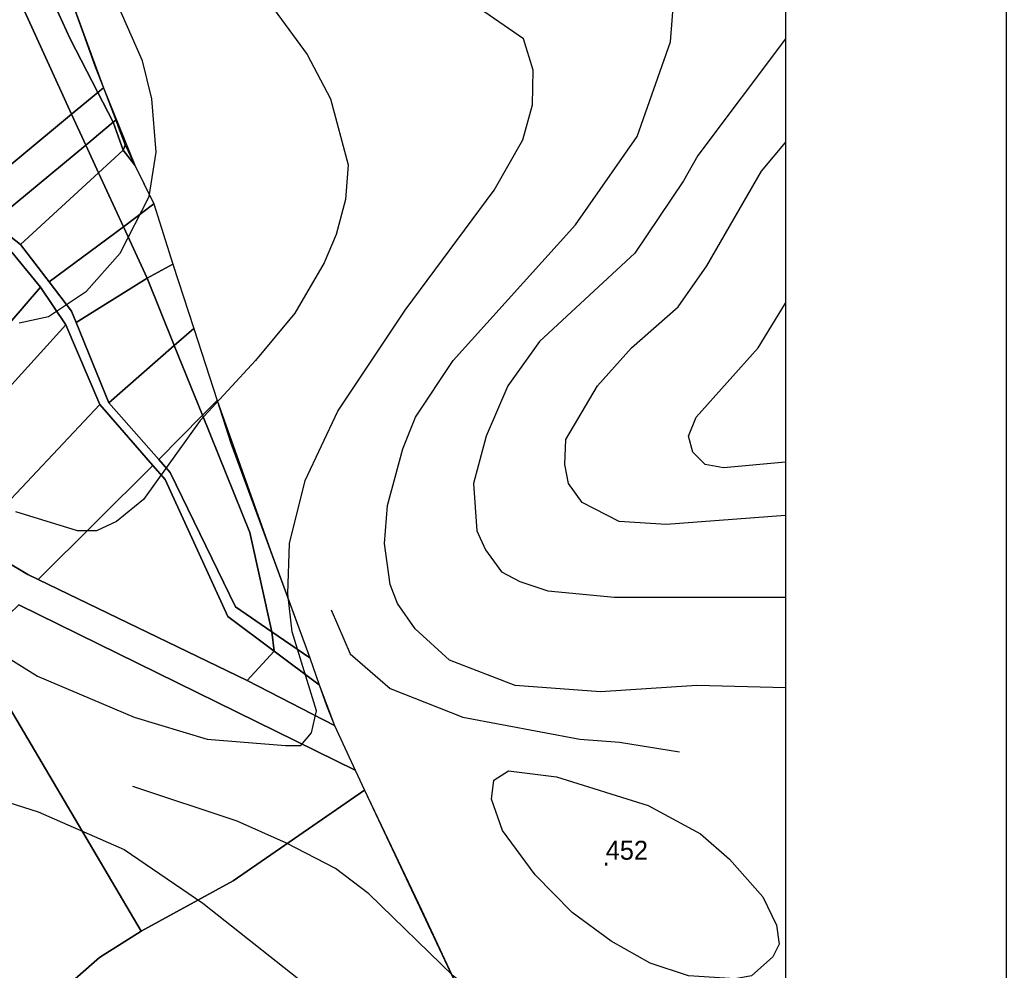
# Model space of a CAD drawing. Extents: x -510989 to -501240, y -1184665 to -1176098.
# Drawn here: x -508331.7 to -508019.1, y -1180014.3 to -1179713 of the extents above; entities that cross this region are included whole.
import ezdxf

# ---------------------------------------------------------------- set-up
doc = ezdxf.new("R2010")
doc.units = 0
for name, color, linetype in [('lesni_pozemek', 7, 'Continuous'), ('ostatni_plocha_x_ostatni_komunikace', 7, 'Continuous'), ('ostatni_plocha_x_silnice', 7, 'Continuous'), ('popis', 7, 'Continuous'), ('rozpiska', 7, 'Continuous'), ('vrstevnice_01', 7, 'Continuous'), ('vrstevnice_02', 7, 'Continuous'), ('vrstevnice_03', 7, 'Continuous'), ('vrstevnice_05', 7, 'Continuous')]:
    doc.layers.add(name, color=color, linetype=linetype)

msp = doc.modelspace()

# ---------------------------------------------------------------- linework, layer by layer
at = {"layer": 'lesni_pozemek'}
for points in [[(-508323.04, -1179685.4), (-508311.57, -1179717.24), (-508307.73, -1179727.9), (-508305.17, -1179734.59), (-508306.93, -1179736.06), (-508315.72, -1179719.07), (-508328.5, -1179691.06)], [(-508335.49, -1179698.31), (-508315.24, -1179742.94), (-508348.72, -1179770.69), (-508349.45, -1179770.12), (-508374.33, -1179736.49)], [(-508306.93, -1179736.06), (-508305.17, -1179734.59), (-508301.26, -1179744.83), (-508302.06, -1179745.49)], [(-508310.75, -1179752.69), (-508340.36, -1179777.21), (-508348.72, -1179770.69), (-508315.24, -1179742.94)], [(-508302.06, -1179745.49), (-508301.26, -1179744.83), (-508301.01, -1179745.49), (-508300.82, -1179745.98), (-508300.48, -1179746.87), (-508298.23, -1179752.78), (-508298.86, -1179754.33)], [(-508306.69, -1179761.51), (-508331.42, -1179784.18), (-508340.36, -1179777.21), (-508310.75, -1179752.69)], [(-508298.86, -1179754.33), (-508298.23, -1179752.78), (-508297.34, -1179754.61), (-508296.57, -1179756.18), (-508295.18, -1179759.04)], [(-508298.83, -1179778.58), (-508322.34, -1179796.08), (-508331.42, -1179784.18), (-508306.69, -1179761.51)], [(-508291.31, -1179794.91), (-508313.8, -1179808.92), (-508315.24, -1179805.39), (-508322.34, -1179796.08), (-508298.83, -1179778.58)], [(-508334.12, -1179786.6), (-508325.1, -1179797.79), (-508353.02, -1179830.13), (-508377.34, -1179854.07), (-508388.85, -1179845.53), (-508355.81, -1179815.14)], [(-508291.31, -1179794.91), (-508282.83, -1179815.88), (-508282.69, -1179816.22), (-508303.46, -1179834.36), (-508313.8, -1179808.92)], [(-508325.1, -1179797.79), (-508317.01, -1179809.73), (-508365.34, -1179862.96), (-508377.34, -1179854.07), (-508353.02, -1179830.13)], [(-508317.01, -1179809.73), (-508306.28, -1179834.94), (-508346.11, -1179877.21), (-508365.34, -1179862.96)], [(-508282.69, -1179816.22), (-508273.74, -1179838.34), (-508287.58, -1179852.38), (-508303.46, -1179834.36)], [(-508306.28, -1179834.94), (-508289.48, -1179854.27), (-508325.79, -1179890.38), (-508329.1, -1179888.78), (-508336.21, -1179884.55), (-508346.11, -1179877.21)], [(-508273.74, -1179838.34), (-508258.72, -1179875.46), (-508251.76, -1179906.97), (-508263.28, -1179899.04), (-508283.99, -1179856.46), (-508287.58, -1179852.38)], [(-508289.48, -1179854.27), (-508285.58, -1179858.75), (-508265.71, -1179902.1), (-508251.05, -1179913.07), (-508259.65, -1179922.4), (-508325.79, -1179890.38)], [(-508347.37, -1179913.24), (-508331.91, -1179898.4), (-508225.42, -1179950.88), (-508222.42, -1179957.19), (-508264.07, -1179985.88), (-508293.14, -1180001.85), (-508338.56, -1179924.99)], [(-508338.56, -1179924.99), (-508293.14, -1180001.85), (-508306.41, -1180010.22), (-508325.34, -1180026.8), (-508351.58, -1180000.65), (-508360.15, -1179982.23), (-508367.63, -1179961.39), (-508373.72, -1179938.52), (-508347.37, -1179913.24)], [(-508264.07, -1179985.88), (-508222.42, -1179957.19), (-508204.32, -1179995.16), (-508177.34, -1180053.09), (-508152.46, -1180106.83), (-508173.6, -1180123.17), (-508192.01, -1180134.69), (-508215.78, -1180151.38), (-508240.41, -1180170.53), (-508260.19, -1180138.45), (-508277.13, -1180118.72), (-508286.73, -1180111.41), (-508303.87, -1180065.86), (-508325.34, -1180026.8), (-508306.41, -1180010.22), (-508293.14, -1180001.85)]]:
    msp.add_lwpolyline(points, close=True, dxfattribs=at)
at = {"layer": 'ostatni_plocha_x_ostatni_komunikace'}
for points in [[(-508328.5, -1179691.06), (-508315.72, -1179719.07), (-508306.93, -1179736.06), (-508315.24, -1179742.94), (-508335.49, -1179698.31)], [(-508315.24, -1179742.94), (-508306.93, -1179736.06), (-508302.06, -1179745.49), (-508310.75, -1179752.69)], [(-508302.06, -1179745.49), (-508298.86, -1179754.33), (-508306.69, -1179761.51), (-508310.75, -1179752.69)], [(-508298.86, -1179754.33), (-508295.18, -1179759.04), (-508289.71, -1179770.24), (-508289.15, -1179771.38), (-508298.83, -1179778.58), (-508306.69, -1179761.51)], [(-508289.15, -1179771.38), (-508283.14, -1179790.49), (-508291.31, -1179794.91), (-508298.83, -1179778.58)], [(-508291.31, -1179794.91), (-508283.14, -1179790.49), (-508276.53, -1179810.83), (-508282.69, -1179816.22), (-508282.83, -1179815.88)], [(-508276.53, -1179810.83), (-508269.12, -1179833.65), (-508273.74, -1179838.34), (-508282.69, -1179816.22)], [(-508269.12, -1179833.65), (-508264.73, -1179847.18), (-508239.71, -1179915.27), (-508251.76, -1179906.97), (-508258.72, -1179875.46), (-508273.74, -1179838.34)], [(-508251.05, -1179913.07), (-508251.76, -1179906.97), (-508239.71, -1179915.27), (-508236.74, -1179923.78)], [(-508259.65, -1179922.4), (-508251.05, -1179913.07), (-508236.74, -1179923.78), (-508234.45, -1179930.36), (-508231.98, -1179936.72)]]:
    msp.add_lwpolyline(points, close=True, dxfattribs=at)
msp.add_lwpolyline([(-508340.36, -1179777.21), (-508331.42, -1179784.18), (-508322.34, -1179796.08), (-508315.24, -1179805.39), (-508313.8, -1179808.92), (-508303.46, -1179834.36), (-508287.58, -1179852.38), (-508283.99, -1179856.46), (-508263.28, -1179899.04), (-508251.76, -1179906.97), (-508251.05, -1179913.07), (-508265.71, -1179902.1), (-508285.58, -1179858.75), (-508289.48, -1179854.27), (-508306.28, -1179834.94), (-508317.01, -1179809.73), (-508325.1, -1179797.79), (-508334.12, -1179786.6)], dxfattribs=at)
at = {"layer": 'ostatni_plocha_x_silnice'}
msp.add_lwpolyline([(-508336.21, -1179884.55), (-508329.1, -1179888.78), (-508325.79, -1179890.38), (-508259.65, -1179922.4), (-508231.98, -1179936.72), (-508225.42, -1179950.88), (-508331.91, -1179898.4)], dxfattribs=at)
at = {"layer": 'popis'}
msp.add_lwpolyline([(-508323.04, -1179685.4), (-508305.17, -1179734.59), (-508295.18, -1179759.04), (-508289.15, -1179771.38), (-508283.14, -1179790.49), (-508276.53, -1179810.83), (-508269.12, -1179833.65), (-508252.22, -1179881.23), (-508239.71, -1179915.27), (-508236.74, -1179923.78), (-508231.98, -1179936.72), (-508225.42, -1179950.88), (-508222.42, -1179957.19), (-508190.83, -1180024.12)], dxfattribs=at)
at = {"layer": 'rozpiska'}
for points in [[(-508019.09, -1176098), (-508019.09, -1184498), (-510989.09, -1184498), (-510989.09, -1176098)], [(-508089.09, -1176168), (-508089.09, -1184428), (-510919.09, -1184428), (-510919.09, -1176168)]]:
    msp.add_lwpolyline(points, close=True, dxfattribs=at)
at = {"layer": 'vrstevnice_01'}
for points in [[(-508331.81, -1179809), (-508322.5, -1179807), (-508310.5, -1179799), (-508299.81, -1179787), (-508290.69, -1179769), (-508288.41, -1179755), (-508289.81, -1179738), (-508292.81, -1179726), (-508309, -1179689)], [(-508370.91, -1179893), (-508326, -1179921), (-508295.41, -1179934), (-508272.31, -1179941), (-508247.5, -1179943), (-508242.59, -1179943), (-508239.19, -1179939), (-508237.59, -1179932), (-508245.31, -1179907), (-508246.69, -1179895), (-508246.19, -1179879), (-508241.19, -1179859), (-508230.91, -1179837), (-508209.59, -1179805), (-508181.31, -1179767), (-508172.31, -1179751), (-508169.19, -1179740), (-508169, -1179729), (-508172, -1179719), (-508211.09, -1179692)], [(-508089.09, -1179719.04), (-508116.81, -1179756), (-508121.31, -1179764), (-508136.81, -1179787), (-508167, -1179815), (-508177, -1179829), (-508183.91, -1179845), (-508187.91, -1179860), (-508186.81, -1179875), (-508184.09, -1179881), (-508179, -1179888), (-508173.19, -1179891), (-508164.31, -1179894), (-508143.19, -1179896), (-508089.09, -1179896)], [(-508089.09, -1179853.25), (-508108.69, -1179855), (-508114.5, -1179854), (-508118.41, -1179850), (-508119.81, -1179845), (-508117.31, -1179839), (-508097.69, -1179817), (-508089.09, -1179802.78)], [(-508106.81, -1179979), (-508096.19, -1179991), (-508091.91, -1180000), (-508091.09, -1180006), (-508093, -1180010), (-508099.81, -1180016), (-508105, -1180017), (-508119.81, -1180016), (-508131.91, -1180012), (-508144.31, -1180005), (-508156.59, -1179996), (-508168.31, -1179984), (-508178.69, -1179970), (-508182.19, -1179960), (-508181.41, -1179954), (-508176.81, -1179951), (-508161.59, -1179953), (-508132.5, -1179962), (-508116, -1179971), (-508106.81, -1179979)]]:
    msp.add_lwpolyline(points, dxfattribs=at)
at = {"layer": 'vrstevnice_02'}
for points in [[(-508267.59, -1179687), (-508240.59, -1179724), (-508233.19, -1179738), (-508227.59, -1179759), (-508228.41, -1179770), (-508231.41, -1179781), (-508235.19, -1179790), (-508244.5, -1179806), (-508257, -1179821), (-508274.5, -1179840), (-508292.5, -1179865), (-508301, -1179872), (-508307.31, -1179875), (-508313.41, -1179875), (-508332.91, -1179869)], [(-508089.09, -1179924.71), (-508117.09, -1179924), (-508147.69, -1179926), (-508174.69, -1179924), (-508195.5, -1179916), (-508206.41, -1179906), (-508212, -1179898), (-508214.31, -1179892), (-508216.09, -1179879), (-508215.09, -1179867), (-508210.31, -1179849), (-508206.31, -1179839), (-508194.31, -1179821), (-508155.59, -1179778), (-508136, -1179750), (-508125.5, -1179720), (-508124.31, -1179705)], [(-508089.09, -1179870.15), (-508126.81, -1179873), (-508141.69, -1179872), (-508153.41, -1179866), (-508157.81, -1179860), (-508159, -1179854), (-508158.59, -1179846), (-508148.59, -1179829), (-508137.81, -1179817), (-508123.09, -1179804), (-508114, -1179791), (-508096.69, -1179761), (-508089.09, -1179751.88)], [(-508393.81, -1180044), (-508397.69, -1180014), (-508395.81, -1179995), (-508393.19, -1179984), (-508384.91, -1179968), (-508375.91, -1179958), (-508367.81, -1179956), (-508355.91, -1179958), (-508344.81, -1179958), (-508325.81, -1179964), (-508298.59, -1179976), (-508273.69, -1179993), (-508213, -1180041)]]:
    msp.add_lwpolyline(points, dxfattribs=at)
at = {"layer": 'vrstevnice_03'}
for points in [[(-508233, -1179900), (-508227, -1179914), (-508214.31, -1179925), (-508191.31, -1179934), (-508154.19, -1179941), (-508141.59, -1179942), (-508122.59, -1179945)], [(-508136.41, -1180046), (-508154.69, -1180040), (-508176.91, -1180030), (-508194.31, -1180016), (-508221.09, -1179990), (-508231.59, -1179982), (-508247.19, -1179974), (-508262.81, -1179967), (-508295.81, -1179956)]]:
    msp.add_lwpolyline(points, dxfattribs=at)

# ---------------------------------------------------------------- texts
at = {"layer": 'vrstevnice_05'}
for s, p in [('452', (-508145.99, -1179979.22)), ('.', (-508146.99, -1179981.12))]:
    msp.add_text(s, height=6, dxfattribs=at).set_placement(p)

doc.saveas('drawing.dxf')
